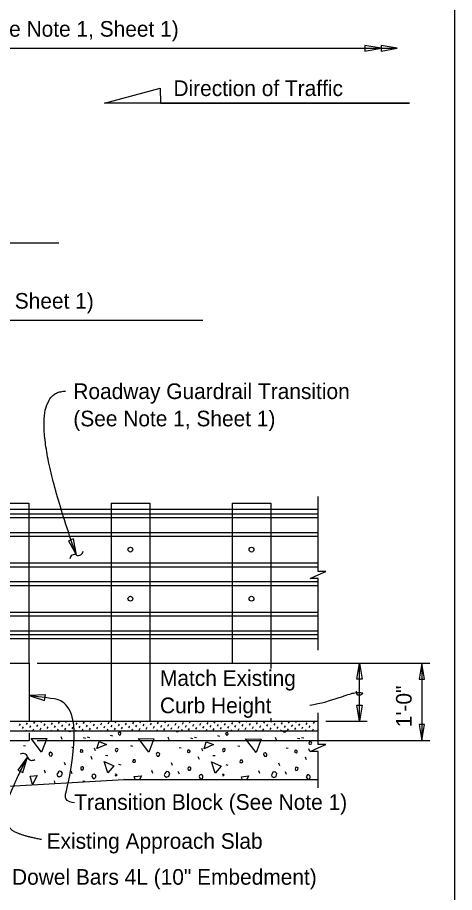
# Model space of a CAD drawing. Extents: x 21665 to 21741.5, y 56121.9 to 56164.2.
# Drawn here: x 21688.53 to 21694.17, y 56139.46 to 56150.74 of the extents above; entities that cross this region are included whole.
import ezdxf

# ---------------------------------------------------------------- set-up
doc = ezdxf.new("R2010")
doc.units = 0
for name, color, linetype in [('Border', 7, 'Continuous'), ('Dimension', 7, 'Continuous'), ('ExistSuperStruct', 7, 'Continuous'), ('Miscellaneous', 7, 'Continuous'), ('SteelMisc_h', 7, 'Continuous'), ('StrMiscConc', 7, 'Continuous'), ('StrMiscConc_h', 7, 'Continuous'), ('TextStructures', 7, 'Continuous')]:
    doc.layers.add(name, color=color, linetype=linetype)

msp = doc.modelspace()

# ---------------------------------------------------------------- linework, layer by layer
at = {"layer": 'Border'}
msp.add_line((21694.168, 56159.403), (21694.168, 56133.475), dxfattribs=at)
at = {"layer": 'Dimension'}
for p, q in [((21689.65, 56149.637), (21690.372, 56149.829)), ((21690.372, 56149.829), (21690.374, 56149.637)), ((21693.461, 56149.637), (21689.65, 56149.637)), ((21690.374, 56149.637), (21693.587, 56149.637)), ((21693.587, 56149.637), (21693.461, 56149.637)), ((21690.921, 56146.835), (21684.112, 56146.835)), ((21688.782, 56142.419), (21693.848, 56142.419)), ((21692.941, 56141.669), (21692.941, 56142.419)), ((21693.748, 56142.419), (21693.748, 56141.419)), ((21692.507, 56141.669), (21693.041, 56141.669)), ((21688.782, 56141.419), (21693.848, 56141.419))]:
    msp.add_line(p, q, dxfattribs=at)
for points in [[(21673.826, 56150.343), (21679.43, 56150.343), (21679.43, 56150.447), (21679.475, 56150.343), (21679.52, 56150.24), (21679.52, 56150.343), (21693.43, 56150.343)], [(21677.369, 56147.835), (21689.063, 56147.835)], [(21692.407, 56142.586), (21692.407, 56143.509), (21692.304, 56143.509), (21692.407, 56143.554), (21692.51, 56143.599), (21692.407, 56143.599), (21692.407, 56144.564)], [(21692.407, 56140.812), (21692.407, 56141.279), (21692.304, 56141.279), (21692.407, 56141.324), (21692.51, 56141.369), (21692.407, 56141.369), (21692.407, 56141.777)]]:
    msp.add_lwpolyline(points, dxfattribs=at)
for points in [[(21693.221, 56150.343), (21693.013, 56150.378), (21693.013, 56150.308)], [(21693.43, 56150.343), (21693.221, 56150.378), (21693.221, 56150.308)], [(21689.289, 56143.811), (21689.252, 56144.019), (21689.186, 56143.995)], [(21692.941, 56142.419), (21692.976, 56142.21), (21692.906, 56142.21)], [(21693.748, 56142.419), (21693.713, 56142.21), (21693.783, 56142.21)], [(21688.679, 56142.002), (21688.88, 56141.937), (21688.89, 56142.007)], [(21692.941, 56141.669), (21692.906, 56141.877), (21692.976, 56141.877)], [(21693.748, 56141.419), (21693.783, 56141.627), (21693.713, 56141.627)], [(21688.659, 56141.209), (21688.536, 56141.037), (21688.6, 56141.006)]]:
    msp.add_lwpolyline(points, close=True, dxfattribs=at)
for centre, start, end in [((21689.264, 56143.758), 63.8956, 175.6228), ((21689.316, 56143.865), 243.8956, 355.6228), ((21688.601, 56141.194), 14.5413, 126.2686), ((21688.716, 56141.224), 194.5413, 306.2686)]:
    msp.add_arc(centre, 0.0596, start, end, dxfattribs=at)
for points, degree in [([(21689.289, 56143.811), (21688.533, 56145.923), (21689.149, 56145.923)], 2), ([(21689.265, 56140.618), (21689.234, 56140.621), (21689.104, 56140.647), (21689.197, 56140.829), (21689.313, 56141.733), (21689.081, 56141.961), (21689.03, 56141.951), (21688.679, 56142.002)], 3), ([(21692.301, 56141.876), (21692.437, 56141.896), (21692.733, 56141.988), (21692.863, 56142.041), (21693.01, 56142.041), (21692.961, 56141.999), (21692.905, 56141.999), (21692.905, 56142.055)], 3), ([(21688.841, 56140.143), (21688.504, 56140.205), (21688.366, 56140.371), (21688.366, 56140.627), (21688.659, 56141.209)], 2)]:
    msp.add_open_spline(points, degree=degree, dxfattribs=at)
at = {"layer": 'ExistSuperStruct'}
for p, q in [((21684.682, 56141.669), (21692.407, 56141.669)), ((21684.682, 56141.544), (21692.407, 56141.544)), ((21685.682, 56140.669), (21689.902, 56140.919)), ((21689.902, 56140.919), (21692.407, 56140.919))]:
    msp.add_line(p, q, dxfattribs=at)
at = {"layer": 'Miscellaneous'}
for p, q in [((21688.174, 56144.481), (21688.674, 56144.481)), ((21688.674, 56144.481), (21688.674, 56142.419)), ((21689.736, 56144.481), (21689.736, 56141.669)), ((21689.736, 56144.481), (21690.236, 56144.481)), ((21690.236, 56144.481), (21690.236, 56141.669)), ((21691.299, 56144.481), (21691.799, 56144.481)), ((21691.299, 56144.481), (21691.299, 56142.41)), ((21691.799, 56144.481), (21691.799, 56142.348)), ((21683.109, 56144.342), (21692.407, 56144.342)), ((21683.109, 56144.294), (21692.407, 56144.294)), ((21683.109, 56144.101), (21692.407, 56144.101)), ((21683.109, 56144.053), (21692.407, 56144.053)), ((21683.109, 56143.709), (21692.407, 56143.709)), ((21683.109, 56143.661), (21692.407, 56143.661)), ((21683.109, 56143.468), (21692.407, 56143.468)), ((21683.109, 56143.42), (21692.407, 56143.42)), ((21683.109, 56143.076), (21692.407, 56143.076)), ((21683.109, 56143.028), (21692.407, 56143.028)), ((21683.109, 56142.835), (21692.407, 56142.835)), ((21683.109, 56142.787), (21692.407, 56142.787)), ((21688.607, 56141.667), (21688.608, 56141.669)), ((21688.74, 56141.64), (21688.753, 56141.663)), ((21688.834, 56141.653), (21688.842, 56141.669)), ((21688.927, 56141.666), (21688.928, 56141.669)), ((21689.153, 56141.652), (21689.162, 56141.669)), ((21689.246, 56141.665), (21689.248, 56141.669)), ((21689.472, 56141.651), (21689.482, 56141.669)), ((21689.565, 56141.664), (21689.568, 56141.669)), ((21689.792, 56141.65), (21689.803, 56141.669)), ((21689.885, 56141.663), (21689.888, 56141.669)), ((21690.111, 56141.649), (21690.123, 56141.669)), ((21690.204, 56141.662), (21690.208, 56141.669)), ((21690.43, 56141.647), (21690.443, 56141.669)), ((21690.523, 56141.66), (21690.528, 56141.669)), ((21690.75, 56141.646), (21690.763, 56141.669)), ((21690.843, 56141.659), (21690.848, 56141.669)), ((21691.069, 56141.645), (21691.082, 56141.667)), ((21691.162, 56141.658), (21691.168, 56141.669)), ((21691.389, 56141.644), (21691.401, 56141.666)), ((21691.482, 56141.657), (21691.488, 56141.669)), ((21691.708, 56141.643), (21691.721, 56141.665)), ((21691.799, 56141.707), (21691.799, 56141.669)), ((21691.801, 56141.656), (21691.809, 56141.669)), ((21692.027, 56141.642), (21692.04, 56141.664)), ((21692.12, 56141.654), (21692.129, 56141.669)), ((21692.213, 56141.667), (21692.214, 56141.669)), ((21692.347, 56141.64), (21692.36, 56141.663)), ((21688.554, 56141.614), (21688.567, 56141.637)), ((21688.594, 56141.574), (21688.607, 56141.597)), ((21688.64, 56141.544), (21688.647, 56141.557)), ((21688.647, 56141.627), (21688.66, 56141.65)), ((21688.687, 56141.587), (21688.7, 56141.61)), ((21688.727, 56141.547), (21688.74, 56141.57)), ((21688.78, 56141.6), (21688.793, 56141.623)), ((21688.821, 56141.56), (21688.834, 56141.583)), ((21688.874, 56141.613), (21688.887, 56141.636)), ((21688.914, 56141.573), (21688.927, 56141.596)), ((21688.96, 56141.544), (21688.967, 56141.555)), ((21688.967, 56141.626), (21688.98, 56141.649)), ((21689.007, 56141.586), (21689.02, 56141.609)), ((21689.047, 56141.546), (21689.06, 56141.568)), ((21689.06, 56141.639), (21689.073, 56141.662)), ((21689.1, 56141.599), (21689.113, 56141.621)), ((21689.14, 56141.559), (21689.153, 56141.581)), ((21689.193, 56141.612), (21689.206, 56141.634)), ((21689.233, 56141.572), (21689.246, 56141.594)), ((21689.28, 56141.544), (21689.286, 56141.554)), ((21689.286, 56141.625), (21689.299, 56141.647)), ((21689.326, 56141.585), (21689.339, 56141.607)), ((21689.366, 56141.545), (21689.379, 56141.567)), ((21689.379, 56141.638), (21689.392, 56141.66)), ((21689.419, 56141.598), (21689.432, 56141.62)), ((21689.459, 56141.558), (21689.472, 56141.58)), ((21689.512, 56141.611), (21689.525, 56141.633)), ((21689.552, 56141.571), (21689.565, 56141.593)), ((21689.6, 56141.544), (21689.605, 56141.553)), ((21689.605, 56141.624), (21689.618, 56141.646)), ((21689.646, 56141.584), (21689.658, 56141.606)), ((21689.686, 56141.544), (21689.699, 56141.566)), ((21689.699, 56141.637), (21689.711, 56141.659)), ((21689.739, 56141.597), (21689.752, 56141.619)), ((21689.779, 56141.557), (21689.792, 56141.579)), ((21689.832, 56141.61), (21689.845, 56141.632)), ((21689.872, 56141.57), (21689.885, 56141.592)), ((21689.92, 56141.544), (21689.925, 56141.552)), ((21689.925, 56141.623), (21689.938, 56141.645)), ((21689.965, 56141.583), (21689.978, 56141.605)), ((21690.006, 56141.544), (21690.018, 56141.565)), ((21690.018, 56141.636), (21690.031, 56141.658)), ((21690.058, 56141.596), (21690.071, 56141.618)), ((21690.098, 56141.555), (21690.111, 56141.578)), ((21690.151, 56141.609), (21690.164, 56141.631)), ((21690.191, 56141.568), (21690.204, 56141.591)), ((21690.24, 56141.544), (21690.244, 56141.551)), ((21690.244, 56141.621), (21690.257, 56141.644)), ((21690.284, 56141.581), (21690.297, 56141.604)), ((21690.326, 56141.544), (21690.337, 56141.564)), ((21690.337, 56141.634), (21690.35, 56141.657)), ((21690.377, 56141.594), (21690.39, 56141.617)), ((21690.417, 56141.554), (21690.43, 56141.577)), ((21690.47, 56141.607), (21690.483, 56141.63)), ((21690.511, 56141.567), (21690.523, 56141.59)), ((21690.564, 56141.62), (21690.577, 56141.643)), ((21690.604, 56141.58), (21690.617, 56141.603)), ((21690.646, 56141.544), (21690.657, 56141.563)), ((21690.657, 56141.633), (21690.67, 56141.656)), ((21690.697, 56141.593), (21690.71, 56141.616)), ((21690.737, 56141.553), (21690.75, 56141.576)), ((21690.79, 56141.606), (21690.803, 56141.629)), ((21690.83, 56141.566), (21690.843, 56141.588)), ((21690.883, 56141.619), (21690.896, 56141.642)), ((21690.923, 56141.579), (21690.936, 56141.601)), ((21690.966, 56141.544), (21690.976, 56141.561)), ((21690.976, 56141.632), (21690.989, 56141.654)), ((21691.016, 56141.592), (21691.029, 56141.614)), ((21691.056, 56141.552), (21691.069, 56141.574)), ((21691.109, 56141.605), (21691.122, 56141.627)), ((21691.149, 56141.565), (21691.162, 56141.587)), ((21691.202, 56141.618), (21691.215, 56141.64)), ((21691.242, 56141.578), (21691.255, 56141.6)), ((21691.286, 56141.544), (21691.295, 56141.56)), ((21691.295, 56141.631), (21691.308, 56141.653)), ((21691.335, 56141.591), (21691.348, 56141.613)), ((21691.376, 56141.551), (21691.389, 56141.573)), ((21691.429, 56141.604), (21691.442, 56141.626)), ((21691.469, 56141.564), (21691.482, 56141.586)), ((21691.522, 56141.617), (21691.535, 56141.639)), ((21691.562, 56141.577), (21691.575, 56141.599)), ((21691.606, 56141.544), (21691.615, 56141.559)), ((21691.615, 56141.63), (21691.628, 56141.652)), ((21691.655, 56141.59), (21691.668, 56141.612)), ((21691.695, 56141.55), (21691.708, 56141.572)), ((21691.748, 56141.603), (21691.761, 56141.625)), ((21691.788, 56141.563), (21691.801, 56141.585)), ((21691.841, 56141.616), (21691.854, 56141.638)), ((21691.881, 56141.576), (21691.894, 56141.598)), ((21691.926, 56141.544), (21691.934, 56141.558)), ((21691.934, 56141.629), (21691.947, 56141.651)), ((21691.974, 56141.588), (21691.987, 56141.611)), ((21692.014, 56141.548), (21692.027, 56141.571)), ((21692.067, 56141.601), (21692.08, 56141.624)), ((21692.107, 56141.561), (21692.12, 56141.584)), ((21692.16, 56141.614), (21692.173, 56141.637)), ((21692.201, 56141.574), (21692.213, 56141.597)), ((21692.246, 56141.544), (21692.254, 56141.557)), ((21692.254, 56141.627), (21692.267, 56141.65)), ((21692.294, 56141.587), (21692.307, 56141.61)), ((21692.334, 56141.547), (21692.347, 56141.57)), ((21688.554, 56141.544), (21688.554, 56141.544)), ((21689.104, 56141.432), (21689.091, 56141.466)), ((21689.378, 56141.459), (21689.406, 56141.452)), ((21689.429, 56141.468), (21689.458, 56141.461)), ((21689.725, 56141.487), (21689.755, 56141.482)), ((21690.487, 56141.429), (21690.475, 56141.462)), ((21690.56, 56141.544), (21690.564, 56141.55)), ((21690.761, 56141.455), (21690.789, 56141.448)), ((21690.813, 56141.465), (21690.841, 56141.457)), ((21690.88, 56141.544), (21690.883, 56141.548)), ((21691.108, 56141.484), (21691.138, 56141.478)), ((21691.2, 56141.544), (21691.202, 56141.547)), ((21691.52, 56141.544), (21691.522, 56141.546)), ((21691.84, 56141.544), (21691.841, 56141.545)), ((21691.87, 56141.425), (21691.858, 56141.459)), ((21692.144, 56141.452), (21692.173, 56141.445)), ((21692.16, 56141.544), (21692.16, 56141.544)), ((21692.196, 56141.461), (21692.224, 56141.454)), ((21688.605, 56141.358), (21688.632, 56141.353)), ((21689.231, 56141.333), (21689.257, 56141.328)), ((21689.988, 56141.355), (21690.015, 56141.349)), ((21690.614, 56141.33), (21690.641, 56141.324)), ((21691.372, 56141.351), (21691.398, 56141.346)), ((21691.998, 56141.326), (21692.024, 56141.321)), ((21689.493, 56141.177), (21689.479, 56141.213)), ((21689.535, 56141.287), (21689.523, 56141.32)), ((21689.665, 56141.233), (21689.697, 56141.229)), ((21690.919, 56141.283), (21690.906, 56141.317)), ((21691.048, 56141.229), (21691.08, 56141.225)), ((21692.302, 56141.28), (21692.29, 56141.313)), ((21689.148, 56141.102), (21689.134, 56141.137)), ((21689.833, 56141.114), (21689.861, 56141.107)), ((21690.531, 56141.098), (21690.517, 56141.134)), ((21690.876, 56141.174), (21690.862, 56141.209)), ((21691.216, 56141.111), (21691.244, 56141.103)), ((21691.914, 56141.095), (21691.9, 56141.13)), ((21692.26, 56141.17), (21692.245, 56141.206)), ((21688.892, 56141.001), (21688.877, 56141.036)), ((21689.235, 56140.99), (21689.221, 56141.025)), ((21690.275, 56140.997), (21690.261, 56141.033)), ((21690.618, 56140.986), (21690.604, 56141.022)), ((21691.658, 56140.994), (21691.644, 56141.029)), ((21692.001, 56140.983), (21691.987, 56141.018)), ((21689.017, 56140.868), (21689.005, 56140.902)), ((21689.373, 56140.902), (21689.398, 56140.898))]:
    msp.add_line(p, q, dxfattribs=at)
for points in [[(21688.84, 56141.271), (21688.706, 56141.448), (21688.906, 56141.446), (21688.84, 56141.271)], [(21689.192, 56141.544), (21689.196, 56141.538), (21689.219, 56141.54), (21689.222, 56141.544)], [(21689.836, 56141.499), (21689.847, 56141.489), (21689.858, 56141.496), (21689.865, 56141.507), (21689.861, 56141.524), (21689.852, 56141.526), (21689.84, 56141.524), (21689.829, 56141.514), (21689.836, 56141.499)], [(21690.224, 56141.268), (21690.089, 56141.445), (21690.289, 56141.443), (21690.224, 56141.268)], [(21690.573, 56141.544), (21690.579, 56141.535), (21690.602, 56141.537), (21690.609, 56141.544)], [(21690.758, 56141.541), (21690.757, 56141.544)], [(21690.759, 56141.544), (21690.758, 56141.541)], [(21691.22, 56141.496), (21691.23, 56141.485), (21691.241, 56141.492), (21691.248, 56141.503), (21691.244, 56141.521), (21691.236, 56141.522), (21691.223, 56141.521), (21691.213, 56141.51), (21691.22, 56141.496)], [(21691.607, 56141.264), (21691.472, 56141.441), (21691.672, 56141.439), (21691.607, 56141.264)], [(21691.955, 56141.544), (21691.962, 56141.531), (21691.985, 56141.533), (21691.994, 56141.542), (21691.996, 56141.544)], [(21692.141, 56141.537), (21692.139, 56141.544)], [(21692.145, 56141.544), (21692.141, 56141.537)], [(21689.554, 56141.316), (21689.582, 56141.408), (21689.676, 56141.37), (21689.554, 56141.316)], [(21690.937, 56141.312), (21690.965, 56141.404), (21691.059, 56141.367), (21690.937, 56141.312)], [(21692.298, 56141.373), (21692.311, 56141.371), (21692.323, 56141.376), (21692.327, 56141.387), (21692.321, 56141.396), (21692.311, 56141.403), (21692.298, 56141.408), (21692.291, 56141.394), (21692.288, 56141.383), (21692.298, 56141.373)], [(21688.939, 56141.24), (21688.948, 56141.224), (21688.969, 56141.22), (21688.978, 56141.236), (21688.982, 56141.25), (21688.973, 56141.259), (21688.957, 56141.268), (21688.941, 56141.263), (21688.936, 56141.247), (21688.939, 56141.24)], [(21689.339, 56141.275), (21689.358, 56141.27), (21689.371, 56141.278), (21689.372, 56141.291), (21689.369, 56141.294), (21689.355, 56141.301), (21689.342, 56141.3), (21689.341, 56141.287), (21689.339, 56141.275)], [(21689.801, 56141.28), (21689.808, 56141.28), (21689.822, 56141.287), (21689.828, 56141.303), (21689.826, 56141.312), (21689.812, 56141.319), (21689.794, 56141.309), (21689.79, 56141.298), (21689.794, 56141.287), (21689.801, 56141.28)], [(21690.323, 56141.236), (21690.331, 56141.22), (21690.353, 56141.217), (21690.361, 56141.233), (21690.365, 56141.247), (21690.356, 56141.256), (21690.34, 56141.264), (21690.324, 56141.259), (21690.319, 56141.243), (21690.323, 56141.236)], [(21690.722, 56141.271), (21690.742, 56141.266), (21690.754, 56141.275), (21690.756, 56141.287), (21690.752, 56141.291), (21690.738, 56141.298), (21690.726, 56141.296), (21690.724, 56141.284), (21690.722, 56141.271)], [(21691.184, 56141.277), (21691.191, 56141.277), (21691.206, 56141.284), (21691.211, 56141.3), (21691.209, 56141.309), (21691.195, 56141.316), (21691.177, 56141.305), (21691.174, 56141.294), (21691.177, 56141.284), (21691.184, 56141.277)], [(21691.706, 56141.233), (21691.715, 56141.217), (21691.736, 56141.213), (21691.745, 56141.229), (21691.748, 56141.243), (21691.739, 56141.252), (21691.724, 56141.261), (21691.708, 56141.256), (21691.702, 56141.24), (21691.706, 56141.233)], [(21692.105, 56141.268), (21692.125, 56141.263), (21692.137, 56141.271), (21692.139, 56141.284), (21692.135, 56141.287), (21692.121, 56141.294), (21692.109, 56141.293), (21692.107, 56141.28), (21692.105, 56141.268)], [(21689.696, 56141.002), (21689.649, 56141.149), (21689.774, 56141.094), (21689.696, 56141.002)], [(21690.02, 56141.139), (21690.041, 56141.139), (21690.052, 56141.149), (21690.047, 56141.169), (21690.024, 56141.171), (21690.02, 56141.16), (21690.015, 56141.151), (21690.02, 56141.139), (21690.017, 56141.142)], [(21691.08, 56140.999), (21691.032, 56141.145), (21691.157, 56141.091), (21691.08, 56140.999)], [(21691.404, 56141.135), (21691.425, 56141.135), (21691.435, 56141.146), (21691.43, 56141.165), (21691.407, 56141.167), (21691.404, 56141.157), (21691.398, 56141.148), (21691.404, 56141.135), (21691.4, 56141.139)], [(21689.045, 56140.964), (21689.068, 56140.951), (21689.098, 56140.964), (21689.111, 56141.001), (21689.093, 56141.019), (21689.07, 56141.024), (21689.059, 56141.017), (21689.047, 56140.997), (21689.038, 56140.982), (21689.045, 56140.964)], [(21689.345, 56141.057), (21689.353, 56141.041), (21689.373, 56141.043), (21689.382, 56141.055), (21689.383, 56141.075), (21689.371, 56141.08), (21689.362, 56141.082), (21689.352, 56141.078), (21689.348, 56141.075), (21689.345, 56141.057)], [(21689.795, 56140.967), (21689.815, 56140.976), (21689.808, 56140.983), (21689.795, 56140.988), (21689.79, 56140.976), (21689.795, 56140.967)], [(21690.429, 56140.96), (21690.452, 56140.948), (21690.482, 56140.96), (21690.494, 56140.997), (21690.476, 56141.015), (21690.453, 56141.02), (21690.443, 56141.013), (21690.43, 56140.994), (21690.422, 56140.978), (21690.429, 56140.96)], [(21690.728, 56141.054), (21690.737, 56141.038), (21690.756, 56141.039), (21690.765, 56141.052), (21690.767, 56141.071), (21690.754, 56141.077), (21690.745, 56141.078), (21690.735, 56141.075), (21690.731, 56141.071), (21690.728, 56141.054)], [(21691.812, 56140.957), (21691.835, 56140.944), (21691.865, 56140.957), (21691.877, 56140.994), (21691.86, 56141.012), (21691.837, 56141.017), (21691.826, 56141.01), (21691.814, 56140.99), (21691.805, 56140.974), (21691.812, 56140.957)], [(21692.111, 56141.05), (21692.12, 56141.034), (21692.139, 56141.036), (21692.148, 56141.048), (21692.15, 56141.068), (21692.138, 56141.073), (21692.129, 56141.075), (21692.118, 56141.071), (21692.115, 56141.068), (21692.111, 56141.05)], [(21688.724, 56140.854), (21688.691, 56140.959), (21688.784, 56140.971), (21688.724, 56140.854)], [(21689.489, 56140.958), (21689.5, 56140.937), (21689.518, 56140.926), (21689.532, 56140.937), (21689.539, 56140.947), (21689.539, 56140.969), (21689.523, 56140.985), (21689.504, 56140.983), (21689.495, 56140.974), (21689.489, 56140.958)], [(21689.904, 56140.919), (21689.903, 56140.919), (21689.902, 56140.919)], [(21690.046, 56140.919), (21690.034, 56140.955), (21690.128, 56140.967), (21690.103, 56140.919)], [(21690.873, 56140.955), (21690.883, 56140.933), (21690.901, 56140.923), (21690.915, 56140.933), (21690.922, 56140.944), (21690.922, 56140.965), (21690.906, 56140.981), (21690.887, 56140.979), (21690.878, 56140.97), (21690.873, 56140.955)], [(21691.179, 56140.963), (21691.198, 56140.972), (21691.191, 56140.979), (21691.179, 56140.985), (21691.173, 56140.972), (21691.179, 56140.963)], [(21691.428, 56140.919), (21691.418, 56140.951), (21691.511, 56140.964), (21691.488, 56140.919)], [(21692.256, 56140.951), (21692.267, 56140.93), (21692.284, 56140.919), (21692.298, 56140.93), (21692.306, 56140.94), (21692.306, 56140.962), (21692.29, 56140.978), (21692.27, 56140.976), (21692.261, 56140.967), (21692.256, 56140.951)]]:
    msp.add_lwpolyline(points, dxfattribs=at)
at = {"layer": 'SteelMisc_h'}
for p, q in [((21692.407, 56144.398), (21683.109, 56144.398)), ((21692.407, 56142.731), (21683.109, 56142.731))]:
    msp.add_line(p, q, dxfattribs=at)
for centre in [(21689.986, 56143.881), (21691.549, 56143.881), (21689.986, 56143.248), (21691.549, 56143.248)]:
    msp.add_circle(centre, 0.0312, dxfattribs=at)
at = {"layer": 'StrMiscConc'}
for p, q in [((21685.682, 56142.419), (21688.682, 56142.419)), ((21688.682, 56142.419), (21688.682, 56141.669))]:
    msp.add_line(p, q, dxfattribs=at)
at = {"layer": 'StrMiscConc_h'}
for p in [(21688.682, 56141.521), (21687.81, 56141.419)]:
    msp.add_line(p, (21688.682, 56141.419), dxfattribs=at)

# ---------------------------------------------------------------- texts
at = {"layer": 'Dimension'}
for s, p in [('Roadway Guardrail Transition', (21689.25, 56145.822)), ('(See Note 1, Sheet 1)', (21689.25, 56145.47)), ('Match Existing ', (21690.368, 56142.124)), ('Curb Height', (21690.368, 56141.772)), ('Dowel Bars 4L (10" Embedment)', (21688.459, 56139.561))]:
    msp.add_text(s, height=0.2016, dxfattribs=at).set_placement(p)
at = {"layer": 'TextStructures'}
for s, p in [('Roadway Guardrail Transition (See Note 1, Sheet 1)', (21684.361, 56150.493)), ('End Deck Joint (See Note 2, Sheet 1)', (21685.018, 56146.987)), ('Transition Block (See Note 1)', (21689.262, 56140.526)), ('Existing Approach Slab', (21688.905, 56140.024))]:
    msp.add_text(s, height=0.2016, dxfattribs=at).set_placement(p)
for s, rotation, p in [('Direction of Traffic', 359.9998, (21690.542, 56149.728)), ('1\'-0"', 90, (21693.615, 56141.592))]:
    msp.add_text(s, height=0.2016, rotation=rotation, dxfattribs=at).set_placement(p)

doc.saveas('drawing.dxf')
